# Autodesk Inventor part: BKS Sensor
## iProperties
Created: 2007-02
Part Number: BKS Sensor
Checked By: Alves
Material: nicht zugewiesen
Description: XX BENENNUNG XX
Document SubType Name: Modellieren
Designer: Klein
ME: ST
Title: XX Gruppe XX
Author: Klein
Comments: keine Bemerkung
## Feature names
1. Grundkörper [Extrusion]
2. Rundung_Grundkörper [Fillet]
3. Kontakt [Revolution]
4. Pinvertiefung [Extrusion]
5. Nut [Extrusion]
6. Trennung [Extrusion]
7. Spiegeln_Trennung [Mirror]
8. Aufkleber [Extrusion]
9. Kennzeichnung [Extrusion]
10. Aufnahme_Diodeneinsatz [Extrusion]
11. Diodeneinsatz [Extrusion]
12. Dioden [Extrusion]
13. Diodenkontur [Fillet]
14. Pin [Extrusion]
15. Rundung_Pin [Fillet]
16. Runde Anordnung_Pin [Circular Pattern]
17. Verdrehsicherung [Extrusion]
18. Pin Mitte [Extrusion]
19. Rundung4 [Fillet]
20. Extrusion13
21. Extrusion14
22. Extrusion15
23. Extrusion16
24. Extrusion17
25. Extrusion18
